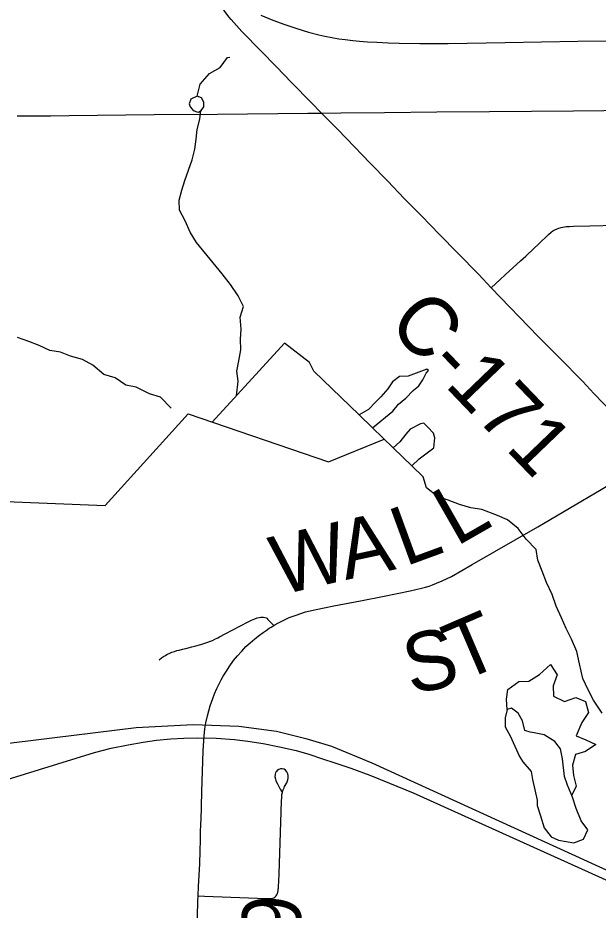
# Model space of a CAD drawing. Extents: x 0 to 34, y 0 to 22.
# Drawn here: x 6.341 to 6.9, y 14.823 to 15.681 of the extents above; entities that cross this region are included whole.
import ezdxf

# ---------------------------------------------------------------- set-up
doc = ezdxf.new("R2010")
doc.units = 0
for name, color, linetype in [('GM_X_County_Road', 7, 'Continuous'), ('GM_X_County_Road_Text', 7, 'Continuous'), ('GM_X_Minor_Lake', 7, 'Continuous'), ('GM_X_Minor_River', 7, 'Continuous'), ('GM_X_Rail_Line', 7, 'Continuous'), ('GM_X_State_Route', 7, 'Continuous'), ('GM_X_Township_Road', 7, 'Continuous')]:
    doc.layers.add(name, color=color, linetype=linetype)

msp = doc.modelspace()

# ---------------------------------------------------------------- linework, layer by layer
at = {"layer": 'GM_X_County_Road'}
for points in [[(6.63403, 15.58975), (6.62403, 15.59992), (6.60523, 15.61888), (6.5901, 15.63444), (6.57582, 15.64916), (6.5572, 15.66835), (6.54674, 15.67978), (6.54456, 15.6824), (6.54198, 15.68577), (6.53996, 15.68875), (6.53851, 15.691), (6.53734, 15.69306), (6.53634, 15.69531), (6.53553, 15.69767), (6.53504, 15.6997), (6.53471, 15.70178), (6.53449, 15.70572)], [(6.34056, 15.58703), (6.37282, 15.58692), (6.39077, 15.58721), (6.47262, 15.58839), (6.53354, 15.58865), (6.62088, 15.58965), (6.63403, 15.58975)], [(6.63403, 15.58975), (6.65259, 15.5899), (6.69465, 15.59023), (6.7451, 15.59095), (6.79568, 15.5913), (6.87673, 15.59199), (6.93521, 15.59246), (6.97838, 15.5924)], [(6.79741, 15.42157), (6.78531, 15.43423), (6.76494, 15.4552), (6.74755, 15.47297), (6.73021, 15.49078), (6.71366, 15.50762), (6.69767, 15.52416), (6.68069, 15.54147), (6.66564, 15.55713), (6.64932, 15.57422), (6.63403, 15.58975)], [(6.89639, 15.31986), (6.88551, 15.33138), (6.86283, 15.35442), (6.84278, 15.37482), (6.79741, 15.42157)], [(6.92391, 15.29103), (6.90591, 15.30978), (6.89639, 15.31986)], [(6.77899, 15.15525), (6.84243, 15.19146), (6.90335, 15.22753), (6.91456, 15.23414)], [(6.58781, 15.09659), (6.58885, 15.09718), (6.59168, 15.09881), (6.59755, 15.10176), (6.60274, 15.10417), (6.60935, 15.10668), (6.61848, 15.10965), (6.62876, 15.11213), (6.63641, 15.1137), (6.64593, 15.11548), (6.67159, 15.1203), (6.69415, 15.12478), (6.71928, 15.12992), (6.72473, 15.13113), (6.73017, 15.13242), (6.73406, 15.13347), (6.73751, 15.13456), (6.74086, 15.13573), (6.74458, 15.13716), (6.74999, 15.13944), (6.759, 15.14384), (6.77899, 15.15525)], [(6.53573, 15.08575), (6.54101, 15.08866), (6.56327, 15.10022), (6.56645, 15.10172), (6.56975, 15.10311), (6.57201, 15.10391), (6.57368, 15.10434), (6.57549, 15.10456), (6.57618, 15.10463), (6.57738, 15.10463), (6.57802, 15.1046), (6.57922, 15.10437), (6.58058, 15.10383), (6.58112, 15.10349), (6.58229, 15.10251), (6.58424, 15.10052), (6.58781, 15.09659)], [(6.51747, 14.89643), (6.51777, 14.90661), (6.51785, 14.90906), (6.5187, 14.93636), (6.51999, 14.97611), (6.52083, 14.99034), (6.52164, 14.99714), (6.52257, 15.00294), (6.52398, 15.00981), (6.52661, 15.01932), (6.5291, 15.02645), (6.53076, 15.03071), (6.533, 15.03585), (6.53498, 15.03995), (6.53723, 15.04427), (6.53923, 15.04777), (6.54223, 15.05269), (6.54503, 15.05694), (6.54925, 15.06288), (6.55303, 15.0675), (6.55699, 15.07201), (6.56106, 15.07625), (6.56529, 15.08006), (6.56968, 15.08376), (6.57427, 15.08735), (6.57783, 15.08998), (6.58058, 15.09193), (6.58357, 15.09394), (6.58541, 15.09512), (6.58781, 15.09659)], [(6.47752, 15.06362), (6.47982, 15.06536), (6.48173, 15.06672), (6.4835, 15.06784), (6.48474, 15.06853), (6.48611, 15.06923), (6.4871, 15.06969), (6.4897, 15.07078), (6.49226, 15.07172), (6.49462, 15.07241), (6.49666, 15.07296), (6.50013, 15.07386), (6.50312, 15.0746), (6.50903, 15.07604), (6.51283, 15.07704), (6.51779, 15.07842), (6.52149, 15.07954), (6.52442, 15.08057), (6.5268, 15.08147), (6.52877, 15.08224), (6.5311, 15.0833), (6.53397, 15.08478), (6.53573, 15.08575)], [(6.51512, 14.83642), (6.51551, 14.84548), (6.51653, 14.86719), (6.517, 14.8796), (6.51732, 14.8901), (6.51741, 14.89439), (6.51747, 14.89643)], [(6.5085, 14.63552), (6.50914, 14.65631), (6.51224, 14.73462), (6.51382, 14.78962), (6.51412, 14.80204), (6.5149, 14.83124), (6.51512, 14.83642)]]:
    msp.add_lwpolyline(points, dxfattribs=at)
at = {"layer": 'GM_X_Minor_Lake'}
for p, q in [((6.50743, 15.59582), (6.50953, 15.59315)), ((6.67002, 15.29935), (6.68296, 15.28686)), ((6.70288, 15.26763), (6.72104, 15.25011)), ((6.83707, 14.94848), (6.84176, 14.92842))]:
    msp.add_line(p, q, dxfattribs=at)
for points in [[(6.50953, 15.59315), (6.51108, 15.59177), (6.51373, 15.59103), (6.51525, 15.59066), (6.51789, 15.5922), (6.52051, 15.59563), (6.52047, 15.60018), (6.51817, 15.60434), (6.514, 15.60582), (6.50796, 15.60312), (6.50648, 15.59856), (6.50743, 15.59582)], [(6.68296, 15.28686), (6.70276, 15.30275), (6.708, 15.30962), (6.71515, 15.31536), (6.72228, 15.32262), (6.72754, 15.32721), (6.73166, 15.33293), (6.73464, 15.3394), (6.73689, 15.34207), (6.73537, 15.3432), (6.72518, 15.33932), (6.71725, 15.33661), (6.70893, 15.33617), (6.70215, 15.33118), (6.69767, 15.32432), (6.69091, 15.31669), (6.68603, 15.31134), (6.67927, 15.30447), (6.67002, 15.29935)], [(6.72104, 15.25011), (6.72813, 15.25691), (6.73565, 15.26265), (6.74205, 15.26763), (6.74311, 15.27712), (6.74194, 15.28166), (6.73622, 15.28731), (6.7324, 15.29145), (6.72938, 15.29067), (6.7192, 15.28566), (6.71508, 15.2807), (6.70945, 15.27345), (6.70288, 15.26763)], [(6.84176, 14.92842), (6.8418, 14.92349), (6.84491, 14.91327), (6.8484, 14.90192), (6.85528, 14.89325), (6.86212, 14.88989), (6.8769, 14.88735), (6.88634, 14.89083), (6.89043, 14.89997), (6.88393, 14.90864), (6.8793, 14.92036), (6.8758, 14.93133), (6.87079, 14.94305), (6.86808, 14.95137), (6.86605, 14.96842), (6.86409, 14.97789), (6.85873, 14.98505), (6.84846, 14.99142), (6.83861, 14.99324), (6.83482, 14.99397), (6.82989, 14.99545), (6.82754, 15.00491), (6.82333, 15.01209), (6.81685, 15.01697), (6.8127, 15.0158), (6.81087, 15.00782), (6.81094, 14.9991), (6.81555, 14.99041), (6.82478, 14.97038), (6.82785, 14.96548), (6.83587, 14.95606), (6.83707, 14.94848)]]:
    msp.add_lwpolyline(points, dxfattribs=at)
at = {"layer": 'GM_X_Minor_River'}
for p, q in [((6.59837, 15.36834), (6.52856, 15.29225)), ((6.62237, 15.34957), (6.59837, 15.36834)), ((6.62659, 15.34126), (6.62237, 15.34957)), ((6.67002, 15.29935), (6.62659, 15.34126)), ((6.4255, 15.21192), (6.50542, 15.30013)), ((6.50542, 15.30013), (6.64052, 15.25415)), ((6.70288, 15.26763), (6.68296, 15.28686)), ((6.64052, 15.25415), (6.69438, 15.27584)), ((6.73185, 15.23968), (6.72104, 15.25011)), ((6.05484, 15.22688), (6.4255, 15.21192))]:
    msp.add_line(p, q, dxfattribs=at)
for points in [[(6.514, 15.60582), (6.51693, 15.6176), (6.52593, 15.62791), (6.53611, 15.63367), (6.54322, 15.6432), (6.54549, 15.6436)], [(6.55195, 15.31774), (6.55362, 15.3316), (6.55241, 15.34144), (6.55422, 15.35132), (6.55603, 15.36195), (6.55595, 15.37219), (6.55664, 15.38167), (6.55541, 15.39342), (6.55873, 15.40368), (6.55373, 15.41388), (6.54608, 15.42482), (6.53805, 15.435), (6.52964, 15.44555), (6.51359, 15.46514), (6.50746, 15.47495), (6.50245, 15.48591), (6.49707, 15.49611), (6.49662, 15.50597), (6.49919, 15.51547), (6.50214, 15.52497), (6.50585, 15.53485), (6.50918, 15.54474), (6.51175, 15.555), (6.51319, 15.56449), (6.51425, 15.57397), (6.51682, 15.58385), (6.51774, 15.59212)], [(6.48911, 15.30569), (6.4788, 15.31623), (6.46818, 15.31956), (6.45526, 15.32591), (6.44541, 15.32773), (6.43513, 15.33486), (6.42413, 15.33818), (6.41346, 15.3472), (6.40358, 15.35243), (6.3922, 15.35576), (6.38233, 15.35947), (6.3721, 15.36129), (6.36184, 15.36614), (6.35197, 15.36986), (6.34096, 15.37357)], [(6.77788, 15.20969), (6.76688, 15.21302), (6.75587, 15.21711), (6.74562, 15.22082), (6.73496, 15.22908), (6.73185, 15.23968)], [(6.90432, 15.01233), (6.89589, 15.02478), (6.8909, 15.0346), (6.88551, 15.04556), (6.88238, 15.05956), (6.88001, 15.07168), (6.87462, 15.0834), (6.86962, 15.0936), (6.865, 15.1038), (6.85999, 15.11514), (6.85612, 15.12649), (6.85073, 15.13782), (6.84648, 15.14879), (6.84224, 15.15937), (6.84064, 15.1696), (6.8311, 15.17977), (6.82345, 15.18995), (6.81317, 15.19821), (6.8033, 15.20231), (6.78849, 15.20826), (6.77788, 15.20969)], [(6.8127, 15.0158), (6.81224, 15.02565), (6.8133, 15.03514), (6.82384, 15.04281), (6.83368, 15.04288), (6.84385, 15.04941), (6.85437, 15.05897), (6.86088, 15.04916), (6.85718, 15.03851), (6.85726, 15.02865), (6.8679, 15.02343), (6.87884, 15.0273), (6.88833, 15.02358), (6.89107, 15.01298), (6.88471, 15.00308), (6.87913, 14.99052), (6.88862, 14.98642), (6.89812, 14.98194), (6.88833, 14.97542), (6.87851, 14.97231), (6.87556, 14.96205), (6.87678, 14.9522), (6.87913, 14.94198), (6.875, 14.93321)]]:
    msp.add_lwpolyline(points, dxfattribs=at)
at = {"layer": 'GM_X_Rail_Line'}
for points in [[(6.2567, 14.97418), (6.4552, 14.99849), (6.51036, 15.00123), (6.5541, 14.99983), (6.59061, 14.99498), (6.6188, 14.98769), (6.64357, 14.98034), (6.68237, 14.96445), (7.09362, 14.7767), (7.19685, 14.72591), (7.29018, 14.68591), (7.3326, 14.66147)], [(6.33102, 14.9483), (6.37981, 14.96344), (6.41507, 14.97423), (6.43133, 14.97841), (6.4476, 14.98163), (6.46193, 14.98421), (6.47481, 14.98614), (6.48882, 14.98743), (6.50122, 14.98808), (6.5141, 14.9884), (6.53229, 14.98808), (6.55001, 14.98679), (6.56289, 14.98534), (6.5777, 14.98308), (6.59348, 14.97986), (6.60942, 14.97616), (6.62182, 14.97278), (6.63486, 14.96843), (6.64662, 14.96457), (6.66208, 14.95925), (6.68043, 14.95249), (6.69943, 14.94476), (6.7223, 14.93558), (6.94048, 14.8372)]]:
    msp.add_lwpolyline(points, dxfattribs=at)
at = {"layer": 'GM_X_State_Route'}
msp.add_lwpolyline([(6.57546, 15.68379), (6.58691, 15.67906), (6.59855, 15.67478), (6.60997, 15.671), (6.62132, 15.66762), (6.63136, 15.66506), (6.63719, 15.66375), (6.64394, 15.66234), (6.65043, 15.66127), (6.65668, 15.66037), (6.66392, 15.65946), (6.67037, 15.65888), (6.67806, 15.6583), (6.68707, 15.65778), (6.69797, 15.6573), (6.70878, 15.65696), (6.72866, 15.65661), (6.75599, 15.6567), (6.81067, 15.65755), (6.8809, 15.65883), (6.9451, 15.65965)], dxfattribs=at)
at = {"layer": 'GM_X_Township_Road'}
for points in [[(6.79741, 15.42157), (6.80589, 15.42966), (6.81088, 15.43418), (6.82565, 15.44737), (6.83072, 15.45199), (6.833, 15.45412), (6.83625, 15.45701), (6.84519, 15.46568), (6.85069, 15.47106), (6.85272, 15.47292), (6.85509, 15.47494), (6.8569, 15.47626), (6.85873, 15.47737), (6.86079, 15.47833), (6.86244, 15.47895), (6.86474, 15.4796), (6.86628, 15.47992), (6.86958, 15.48039), (6.87284, 15.4807), (6.87667, 15.48088), (6.89236, 15.48116), (6.91784, 15.48174)], [(6.58966, 14.83586), (6.59021, 14.83656), (6.59082, 14.8375), (6.59114, 14.8381), (6.5915, 14.83902), (6.59168, 14.83966), (6.5919, 14.84058), (6.59208, 14.84139), (6.59228, 14.84275), (6.59238, 14.84376), (6.5925, 14.84532), (6.59285, 14.85044), (6.59322, 14.85774), (6.59517, 14.91734), (6.59541, 14.92781), (6.59555, 14.93076), (6.59561, 14.93169), (6.59573, 14.93321), (6.59583, 14.93395), (6.596, 14.93496), (6.59618, 14.93584), (6.59647, 14.9368), (6.59704, 14.93851), (6.5978, 14.94031), (6.5984, 14.94156), (6.60036, 14.9453), (6.6011, 14.94712), (6.60141, 14.9482), (6.60168, 14.94974), (6.60174, 14.95106), (6.60171, 14.95232), (6.60148, 14.95376), (6.60064, 14.95577), (6.59928, 14.95734), (6.59793, 14.95818), (6.59614, 14.95861), (6.59437, 14.95852), (6.59271, 14.95802), (6.59133, 14.95715), (6.59041, 14.95619), (6.58998, 14.95554), (6.58954, 14.95466), (6.5892, 14.95355), (6.5891, 14.95283), (6.58906, 14.95141), (6.58916, 14.95047), (6.5893, 14.94961), (6.58954, 14.94873), (6.58996, 14.94754), (6.59035, 14.94658), (6.59141, 14.94431), (6.59314, 14.94093), (6.59407, 14.93921), (6.59558, 14.93657)], [(6.51512, 14.83642), (6.5213, 14.83614), (6.58066, 14.8338), (6.58319, 14.8338), (6.58554, 14.83397), (6.58675, 14.83421), (6.58792, 14.8346), (6.58889, 14.83516), (6.58966, 14.83586)]]:
    msp.add_lwpolyline(points, dxfattribs=at)

# ---------------------------------------------------------------- texts
at = {"layer": 'GM_X_County_Road_Text'}
for s, height, rotation, p in [('C-171', 0.056818, 313.8476, (6.69616, 15.38545)), ('L', 0.05682, 29.8001, (6.76369, 15.17217)), ('L', 0.05682, 20.13301, (6.7143, 15.15312)), ('A', 0.05682, 12.10366, (6.65706, 15.14023)), ('W', 0.05682, 13.04915, (6.59317, 15.12542)), ('T', 0.05682, 23.31254, (6.76827, 15.04172)), ('S', 0.05682, 12.67517, (6.71993, 15.02976)), ('C-159', 0.056818, 87.9948, (6.60768, 14.62932))]:
    msp.add_text(s, height=height, rotation=rotation, dxfattribs=at).set_placement(p)

doc.saveas('drawing.dxf')
